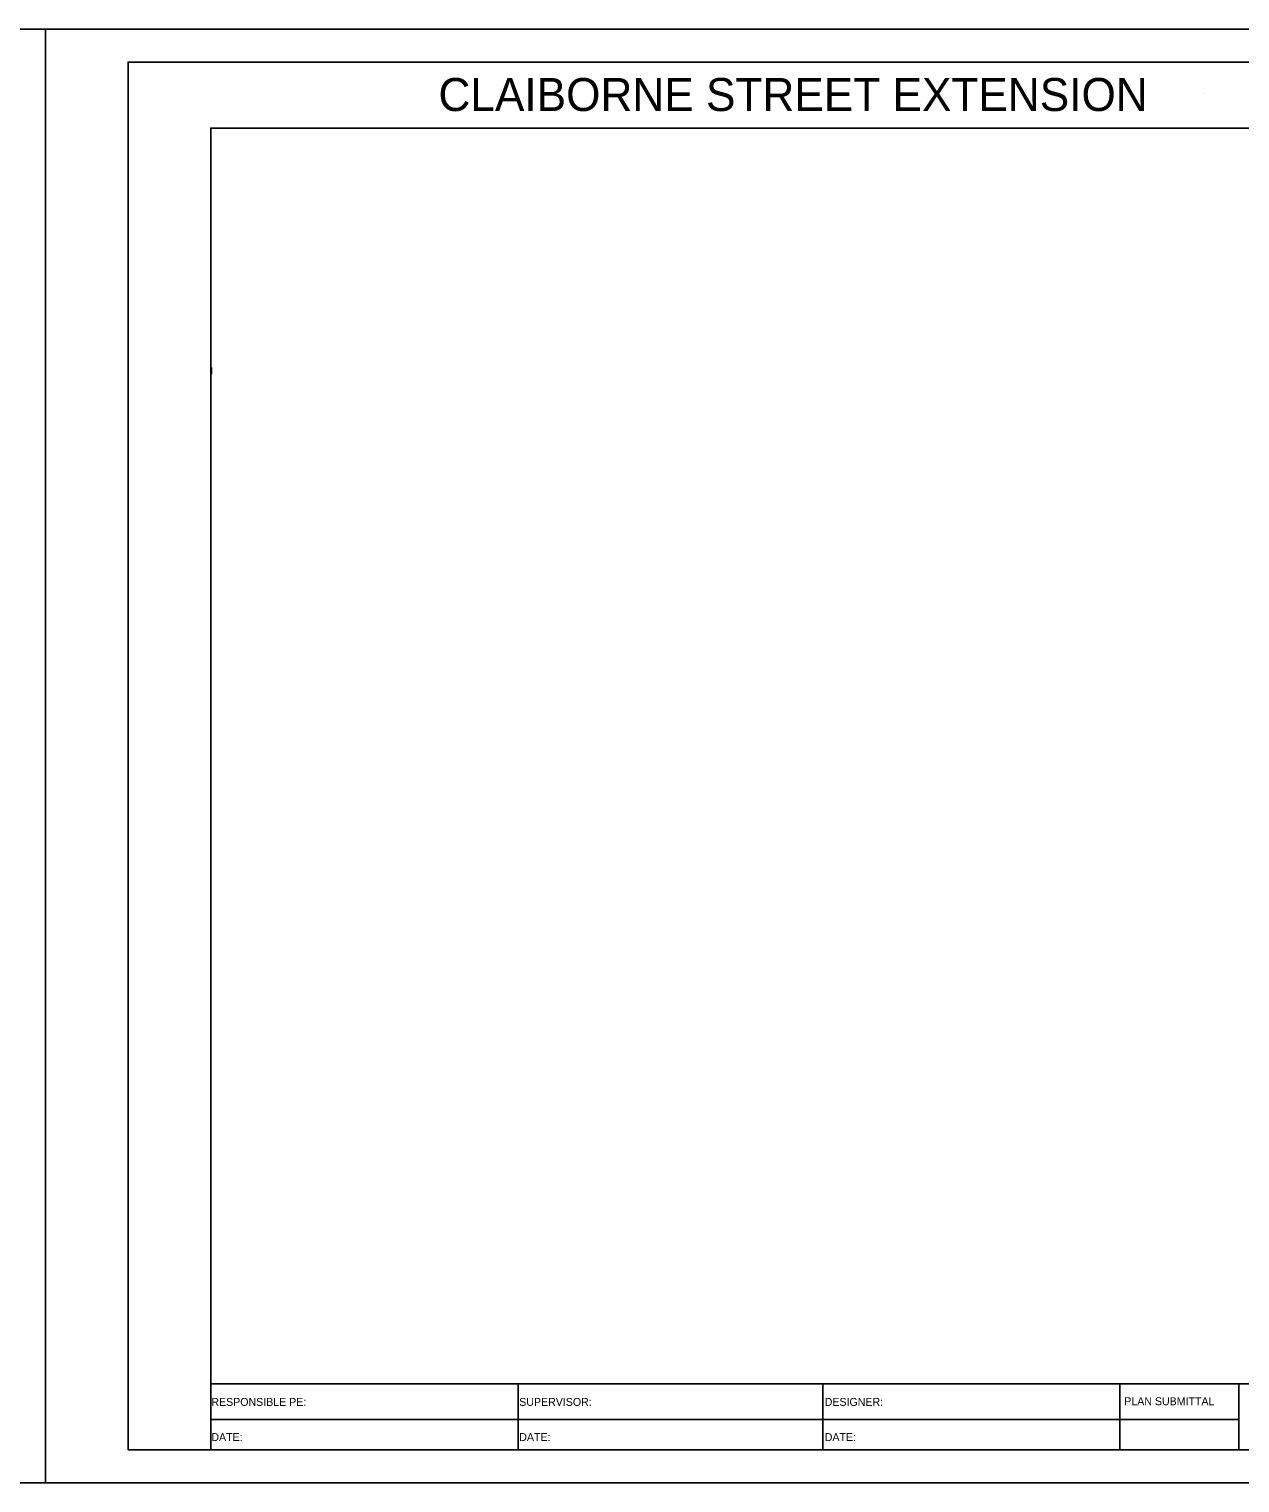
# Model space of a CAD drawing. Extents: x 1797478 to 1803816, y 246529 to 250952.
# Drawn here: x 1803133.5 to 1803316.8, y 250064.4 to 250284.4 of the extents above; entities that cross this region are included whole.
import ezdxf

# ---------------------------------------------------------------- set-up
doc = ezdxf.new("R2010")
doc.units = 0
for name, color, linetype in [('2', 7, 'Continuous'), ('ANNO-SHT', 7, 'Continuous'), ('ANNO-TXT', 7, 'Continuous'), ('AXIS', 7, 'Continuous'), ('DRAINAGE', 7, 'Continuous'), ('Level 1', 7, 'Continuous'), ('Level 62', 7, 'Continuous'), ('SHT-BDR', 7, 'Continuous'), ('SHT-BNDRY', 7, 'Continuous')]:
    doc.layers.add(name, color=color, linetype=linetype)

# ---------------------------------------------------------------- blocks, each defined once
blk = doc.blocks.new('SC47208')
at = {"layer": 'Level 1'}
blk.add_line((0, 0), (0, 0), dxfattribs=at)

msp = doc.modelspace()

# ---------------------------------------------------------------- linework, layer by layer
at = {"layer": '2'}
msp.add_lwpolyline([(1803161.12, 250233.21), (1803161.1, 250232.21)], dxfattribs=at)
msp.add_lwpolyline([(1803161.12, 250233.21), (1803161.1, 250232.21)], dxfattribs=at)
at = {"layer": 'AXIS'}
msp.add_line((1803161, 250189.42), (1803161, 250189.43), dxfattribs=at)
at = {"layer": 'Level 62'}
for points in [[(1802796, 250064.42), (1803136, 250064.42), (1803136, 250284.42), (1802796, 250284.42)], [(1803136, 250064.42), (1803476, 250064.42), (1803476, 250284.42), (1803136, 250284.42)]]:
    msp.add_lwpolyline(points, close=True, dxfattribs=at)
at = {"layer": 'SHT-BDR'}
msp.add_lwpolyline([(1803161, 250079.43), (1803461, 250079.43), (1803461, 250269.43), (1803161, 250269.43)], close=True, dxfattribs=at)
at = {"layer": 'SHT-BNDRY'}
for p, q in [((1803161, 250069.42), (1803161, 250079.43)), ((1803207.52, 250079.43), (1803207.52, 250069.42)), ((1803253.67, 250069.42), (1803253.67, 250079.43)), ((1803298.59, 250069.42), (1803298.59, 250079.43)), ((1803316.63, 250069.42), (1803316.63, 250079.43)), ((1803161, 250074.03), (1803316.63, 250074.03))]:
    msp.add_line(p, q, dxfattribs=at)
msp.add_lwpolyline([(1803148.5, 250069.42), (1803471, 250069.42), (1803471, 250279.42), (1803148.5, 250279.42)], close=True, dxfattribs=at)

# ---------------------------------------------------------------- block references
at = {"layer": 'DRAINAGE', "xscale": 0.2, "yscale": 0.20000000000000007, "rotation": -116.41666666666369}
msp.add_blockref('SC47208', (1803311.32, 250274.62), dxfattribs=at)
msp.add_blockref('SC47208', (1803311.32, 250274.62), dxfattribs=at)

# ---------------------------------------------------------------- texts
at = {"layer": 'ANNO-SHT'}
msp.add_text('           CLAIBORNE STREET EXTENSION           ', height=4.9995, rotation=360, dxfattribs=at).set_placement((1803175.04, 250272.02))
at = {"layer": 'ANNO-TXT'}
for s, p in [('RESPONSIBLE PE:', (1803161.1, 250076.08)), ('SUPERVISOR:', (1803207.7, 250076.08)), ('DESIGNER:', (1803253.94, 250076.08)), ('PLAN SUBMITTAL', (1803299.28, 250076.18)), ('DATE:', (1803161.1, 250070.76)), ('DATE:', (1803207.7, 250070.76)), ('DATE:', (1803253.94, 250070.76))]:
    msp.add_text(s, height=1.2, rotation=360, dxfattribs=at).set_placement(p)

doc.saveas('drawing.dxf')
